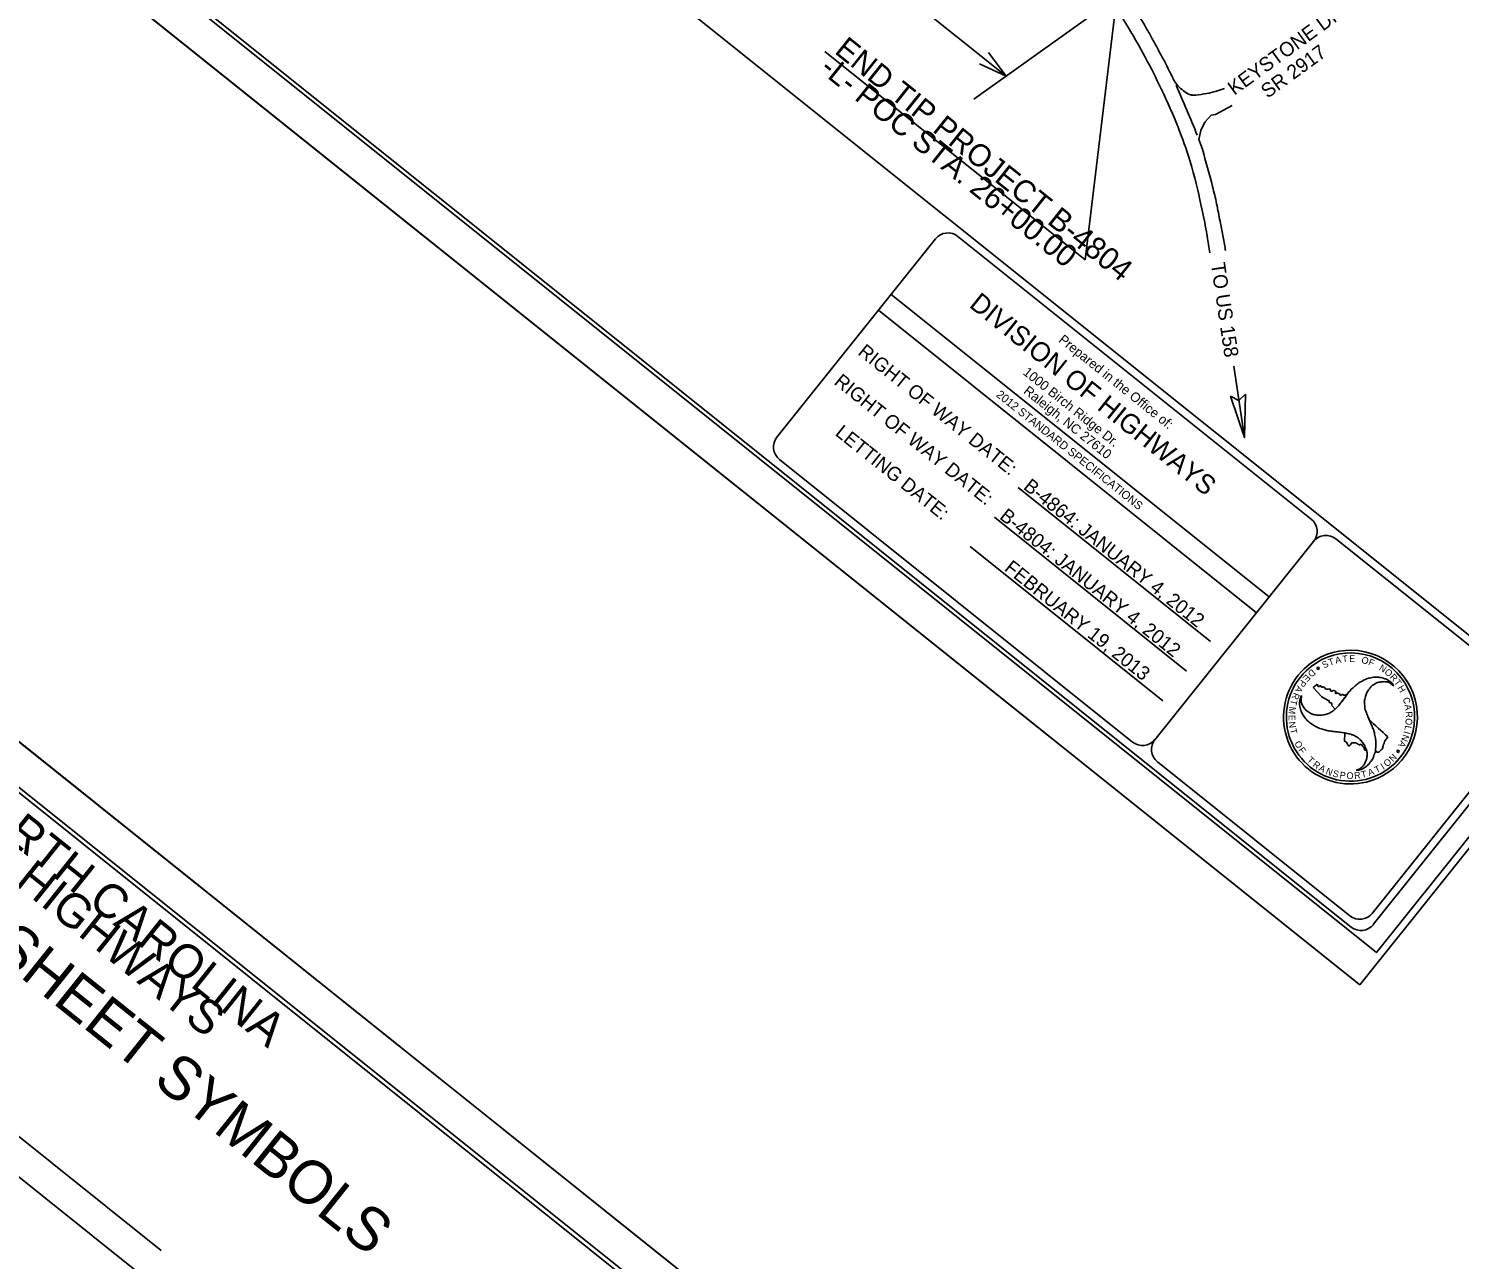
# Model space of a CAD drawing. Extents: x 1730256 to 1738218, y 910410 to 917906.
# Drawn here: x 1733718 to 1735520, y 913560 to 915111 of the extents above; entities that cross this region are included whole.
import ezdxf

# ---------------------------------------------------------------- set-up
doc = ezdxf.new("R2010")
doc.units = 0
for name, color, linetype in [('Old_Level_23', 7, 'Continuous'), ('Old_Level_3', 7, 'Continuous'), ('Old_Level_9', 7, 'Continuous'), ('Prop DSN Text', 7, 'Continuous'), ('Prop Terminator CELL', 7, 'Continuous'), ('Sheet Cutting Line CELL', 7, 'Continuous'), ('Sheet Data Field CELL', 7, 'Continuous'), ('Sheet Plot Border Inside CELL', 7, 'Continuous'), ('Sheet Plot Border Outside CELL', 7, 'Continuous'), ('Sheet Symbology CELL', 7, 'Continuous'), ('Sheet Title CELL', 7, 'Continuous')]:
    doc.layers.add(name, color=color, linetype=linetype)

msp = doc.modelspace()

# ---------------------------------------------------------------- linework, layer by layer
at = {"layer": 'Old_Level_23'}
for p, q in [((1734484.6, 915423.6), (1734949.5, 915051.5)), ((1735088.9, 915151.5), (1734908.9, 915022.4)), ((1735088.9, 915151.5), (1735048.8, 914820)), ((1734720.8, 915082.5), (1735048.8, 914820))]:
    msp.add_line(p, q, dxfattribs=at)
at = {"layer": 'Old_Level_3'}
msp.add_lwpolyline([(1735234.3, 915014.6), (1735213.2, 915003.1), (1735207.5, 915002.3), (1735199.9, 914993.4), (1735194.8, 914983), (1735192.3, 914971.6), (1735196.6, 914959.6)], dxfattribs=at)
msp.add_ellipse((1732344.7, 913726.7), major_axis=(-1157.9, 3394.9), ratio=0.865711, start_param=4.786277, end_param=4.805356, dxfattribs=at)
for points in [[(1735388.4, 915590.4), (1735416.8, 915551.2), (1735441.8, 915513.8), (1735465.3, 915471.6), (1735485, 915425.8), (1735499.5, 915381.4), (1735512.1, 915334.5), (1735524.2, 915290), (1735536.6, 915251.7), (1735553.3, 915211.2), (1735574, 915173.6), (1735599.6, 915136.9), (1735628.5, 915103.2), (1735661.8, 915070.2), (1735681.4, 915051.5)], [(1735374.5, 915580.4), (1735401.4, 915540.4), (1735425.3, 915502.3), (1735446.7, 915462.8), (1735465.8, 915420.2), (1735480.6, 915373.8), (1735493.3, 915328), (1735505.8, 915283.9), (1735518.6, 915242.7), (1735535.2, 915202.7), (1735557.3, 915162.9), (1735584.3, 915124.3), (1735613.8, 915089.7), (1735647.9, 915055.6), (1735667.7, 915037)], [(1734867.9, 915373.1), (1734891.7, 915356.8), (1734930.3, 915326), (1734970.3, 915292), (1735005.3, 915261.3), (1735024.1, 915243.4), (1735033.2, 915234.2), (1735042.1, 915224.8), (1735056.2, 915209.4), (1735069.7, 915193.5), (1735086.7, 915171.4), (1735102.7, 915148.8), (1735126, 915112.1), (1735140.9, 915084.9), (1735155.4, 915057.4), (1735158.1, 915051.7), (1735159.5, 915048.8), (1735160.9, 915045.9), (1735165.9, 915039.4), (1735172.8, 915033), (1735180.6, 915028.3), (1735182.6, 915027.8), (1735184.5, 915027.6), (1735188.4, 915027.7), (1735201.9, 915029.6), (1735214.3, 915032.5), (1735224.6, 915035.9)], [(1734858.2, 915360.7), (1734895.6, 915328.6), (1734934.2, 915297.2), (1734972.7, 915264.8), (1735005.9, 915234.2), (1735039.9, 915198.2), (1735072.4, 915158), (1735096.8, 915123.1), (1735122, 915080.1), (1735142.3, 915040.7), (1735163.9, 914992.3), (1735179.1, 914950.6), (1735193.6, 914895.6), (1735202.8, 914849.7), (1735206.1, 914828.7)], [(1735196.6, 914959.6), (1735209.5, 914912.3), (1735214.6, 914890.6), (1735216.8, 914879.6), (1735218.9, 914868.6), (1735220.7, 914859.7), (1735222.4, 914850.8), (1735225.5, 914833), (1735225.6, 914831.7)]]:
    msp.add_spline(points, degree=3, dxfattribs=at)
at = {"layer": 'Old_Level_9'}
msp.add_line((1735236.1, 914685.8), (1735249.8, 914595.9), dxfattribs=at)
at = {"layer": 'Prop DSN Text'}
msp.add_lwpolyline([(1734927.1, 915081.1), (1734949.5, 915051.5), (1734915.8, 915067)], dxfattribs=at)
at = {"layer": 'Prop Terminator CELL'}
msp.add_lwpolyline([(1735250.8, 914650.7), (1735249.8, 914595.9), (1735232.1, 914648.1), (1735242.6, 914642.7)], close=True, dxfattribs=at)
at = {"layer": 'Sheet Cutting Line CELL'}
for p, q in [((1732765.3, 916010.8), (1735394.8, 913906.4)), ((1734907.9, 913250.5), (1732278.3, 915354.9))]:
    msp.add_line(p, q, dxfattribs=at)
at = {"layer": 'Sheet Data Field CELL'}
msp.add_lwpolyline([(1736769.5, 915624), (1734139.9, 917728.5), (1732765.3, 916010.8), (1735394.8, 913906.4)], close=True, dxfattribs=at)
at = {"layer": 'Sheet Plot Border Inside CELL'}
for points in [[(1732813.6, 916029.6), (1735415.9, 913947), (1736734.4, 915594.6), (1734132.1, 917677.2)], [(1730952, 913656.1), (1733554.3, 911573.5), (1734872.8, 913221.1), (1732270.6, 915303.6)]]:
    msp.add_lwpolyline(points, close=True, dxfattribs=at)
at = {"layer": 'Sheet Plot Border Outside CELL'}
msp.add_lwpolyline([(1730903.7, 913637.3), (1733533.3, 911532.8), (1734907.9, 913250.5), (1732278.3, 915354.9)], close=True, dxfattribs=at)
at = {"layer": 'Sheet Symbology CELL'}
for p, q in [((1733885, 913571.6), (1733564.9, 913827.8)), ((1733860, 913540.4), (1733540, 913796.5))]:
    msp.add_line(p, q, dxfattribs=at)
msp.add_lwpolyline([(1734850.1, 913232.7), (1732507.9, 915107.2), (1731197, 913469.2), (1733539.2, 911594.7)], close=True, dxfattribs=at)
at = {"layer": 'Sheet Title CELL'}
for p, q in [((1733396.2, 916056.6), (1735613.6, 914282.1)), ((1734860.6, 914846.4), (1734660.7, 914596.5)), ((1734888.7, 914849.4), (1735333.7, 914493.3)), ((1735280.9, 914395.3), (1734804.6, 914776.4)), ((1735264.9, 914375.3), (1734788.7, 914756.5)), ((1734934.9, 914639.5), (1734934.9, 914639.5)), ((1734964.6, 914533.1), (1735206.8, 914339.2)), ((1734934.6, 914495.7), (1735176.8, 914301.8)), ((1735364.9, 914468.3), (1735607.3, 914274.3)), ((1734904, 914458.6), (1735146.8, 914264.3)), ((1735136.9, 914215.3), (1735336.8, 914465.2)), ((1735085.6, 914436.2), (1735085.6, 914436.2)), ((1735055.7, 914398.7), (1735055.7, 914398.7)), ((1735340.4, 914305.1), (1735341.7, 914305.8)), ((1735341.8, 914304.9), (1735340.4, 914305.1)), ((1735341.7, 914305.8), (1735341.5, 914307.2)), ((1735341.5, 914307.2), (1735342.6, 914306.2)), ((1735342, 914303.4), (1735341.8, 914304.9)), ((1735342.7, 914304.7), (1735342, 914303.4)), ((1735342.6, 914306.2), (1735343.8, 914306.8)), ((1735344.2, 914304.5), (1735342.7, 914304.7)), ((1735343.8, 914306.8), (1735343.2, 914305.5)), ((1735343.2, 914305.5), (1735344.2, 914304.5)), ((1735336.4, 914281.2), (1735340.2, 914284.6)), ((1735347, 914269.2), (1735336.4, 914281.2)), ((1735355.3, 914264.5), (1735347, 914269.2)), ((1735437.7, 914283.5), (1735437.4, 914283.5)), ((1735437.7, 914283.5), (1735437.4, 914283.5)), ((1735364, 914253.8), (1735359.4, 914258.7)), ((1735406.5, 914241.2), (1735406.5, 914241.2)), ((1735375.7, 914213.3), (1735376.3, 914223.7)), ((1735376.3, 914223.7), (1735376.3, 914223.7)), ((1735442.6, 914201.1), (1735441.3, 914200.5)), ((1735441.3, 914200.5), (1735442.7, 914200.3)), ((1735443.4, 914201.5), (1735442.4, 914202.6)), ((1735442.4, 914202.6), (1735442.6, 914201.1)), ((1735442.7, 914200.3), (1735442.9, 914198.8)), ((1735442.9, 914198.8), (1735443.6, 914200.1)), ((1735444.7, 914202.2), (1735443.4, 914201.5)), ((1735443.6, 914200.1), (1735445.1, 914199.9)), ((1735444, 914200.9), (1735444.7, 914202.2)), ((1735445.1, 914199.9), (1735444, 914200.9)), ((1735441.6, 914182.8), (1735441.6, 914182.8))]:
    msp.add_line(p, q, dxfattribs=at)
for points in [[(1733072.9, 915828.7), (1735383.9, 913979.1)], [(1735412, 913982.3), (1736699.2, 915590.6)], [(1734663.7, 914568.4), (1735108.7, 914212.2)], [(1735410.5, 913996.3), (1735610.4, 914246.2)], [(1735140, 914187.2), (1735382.4, 913993.2)]]:
    msp.add_lwpolyline(points, dxfattribs=at)
for centre, radius, start, end in [((1734876.2, 914833.9), 20, 51.3297, 141.3297), ((1734676.3, 914584), 20, 141.3297, 231.3297), ((1735321.2, 914477.7), 20, 321.3297, 51.3297), ((1735352.4, 914452.7), 20, 51.3297, 141.3297), ((1735383.2, 914243.8), 84.3, 313.7508, 133.7508), ((1735383.2, 914243.8), 80.8, 313.7508, 133.7508), ((1735383.2, 914243.8), 84.3, 133.7508, 313.7508), ((1735383.2, 914243.8), 80.8, 133.7508, 313.7508), ((1735721.7, 914554.9), 444.7, 219.4293, 219.5289), ((1735721.7, 914554.9), 444.7, 224.8684, 229.0744), ((1735121.3, 914227.9), 20, 231.3297, 321.3297), ((1735152.5, 914202.9), 20, 141.3297, 231.3297), ((1735394.9, 914008.9), 20, 231.3297, 321.3297), ((1735396.5, 913994.8), 20, 231.3297, 321.3297)]:
    msp.add_arc(centre, radius, start, end, dxfattribs=at)
for points in [[(1735437.4, 914283.5), (1735436.5, 914285.2), (1735432.5, 914289.1), (1735427.2, 914292), (1735426.7, 914292.1), (1735423.6, 914293.1), (1735419.9, 914293.8), (1735413.6, 914294.1), (1735407.3, 914292.9), (1735404.7, 914292.4), (1735402, 914291.2), (1735396.4, 914288.4), (1735391.6, 914285.1), (1735386.4, 914280.8), (1735382.2, 914276.6), (1735378.6, 914271.7), (1735374.9, 914266.8), (1735371.3, 914262.1), (1735367.4, 914257.3), (1735363.1, 914253.1), (1735362.7, 914252.7), (1735357.3, 914249.1), (1735351.5, 914247.1), (1735345.7, 914246.2), (1735342.8, 914246.1), (1735339.2, 914246.7), (1735337.2, 914246.9), (1735333.2, 914248.4), (1735328.2, 914251.6), (1735324.5, 914255.9), (1735322, 914260.4), (1735321, 914265.5), (1735321.5, 914270.8)], [(1735340.2, 914284.6), (1735340.4, 914285), (1735341.4, 914284.8), (1735342.3, 914282.4), (1735343.9, 914282.3), (1735344.6, 914283), (1735346, 914283), (1735346.9, 914281.6), (1735349.3, 914281.9), (1735350.4, 914281.1), (1735352.4, 914279.1), (1735357.2, 914279), (1735358.3, 914278.1), (1735357.9, 914277.2), (1735358.4, 914276.4), (1735361.4, 914277.3), (1735362, 914277.3), (1735364.6, 914276.2), (1735364.7, 914275.3), (1735363.9, 914274.3), (1735364, 914273.8), (1735365.1, 914273.6), (1735366.9, 914273.8), (1735369.3, 914273), (1735370.8, 914271), (1735372.5, 914272.1), (1735375.9, 914271.4), (1735377.2, 914271.8), (1735378.2, 914272.5)], [(1735390.5, 914176.7), (1735392.4, 914176.7), (1735397.8, 914178.3), (1735402.9, 914181.4), (1735403.4, 914181.7), (1735405.7, 914183.9), (1735408.2, 914186.8), (1735411.6, 914192.1), (1735413.7, 914198.1), (1735414.6, 914200.6), (1735414.9, 914203.7), (1735415.3, 914209.9), (1735414.9, 914215.7), (1735413.6, 914222.3), (1735412.1, 914228), (1735409.7, 914233.6), (1735407.3, 914239.3), (1735405.1, 914244.7), (1735402.8, 914250.5), (1735401.3, 914256.3), (1735401.3, 914256.9), (1735400.7, 914263.4), (1735402, 914269.5), (1735404, 914274.9), (1735405.5, 914277.4), (1735407.7, 914280.2), (1735408.9, 914281.9), (1735412.2, 914284.6), (1735417.5, 914287.3), (1735423, 914288.3), (1735428.2, 914288.3), (1735433.2, 914286.6), (1735437.4, 914283.5), (1735437.7, 914283.5)], [(1735321.5, 914270.8), (1735320.6, 914269.1), (1735319.2, 914263.6), (1735319.3, 914257.7), (1735319.4, 914257.2), (1735320.1, 914253.9), (1735321.4, 914250.4), (1735324.3, 914244.8), (1735328.4, 914240), (1735330.2, 914238), (1735332.7, 914236.2), (1735337.8, 914232.8), (1735343, 914230.2), (1735349.4, 914228), (1735355, 914226.5), (1735361.1, 914225.7), (1735367.3, 914225), (1735373.2, 914224.2), (1735379.2, 914223.2), (1735385, 914221.6), (1735385.6, 914221.4), (1735391.5, 914218.5), (1735396.1, 914214.5), (1735399.7, 914210.1), (1735401.3, 914207.5), (1735402.5, 914204.2), (1735403.4, 914202.2), (1735404.1, 914198), (1735403.8, 914192.1), (1735401.9, 914186.8), (1735399.3, 914182.4), (1735395.3, 914178.9), (1735390.5, 914176.7)], [(1735378.7, 914271.9), (1735378.6, 914271.7), (1735374.9, 914266.8), (1735371.3, 914262.1), (1735367.4, 914257.3), (1735364, 914253.8)], [(1735359.4, 914258.7), (1735359.9, 914260), (1735359.2, 914261.2), (1735357.4, 914261.8), (1735356.5, 914262.8), (1735356.3, 914264.6), (1735355.3, 914264.5)], [(1735414.8, 914201.7), (1735414.9, 914203.7), (1735415.3, 914209.9), (1735414.9, 914215.7), (1735413.6, 914222.3), (1735412.1, 914228), (1735409.7, 914233.6), (1735407.3, 914239.3), (1735406.5, 914241.2)], [(1735403.3, 914202.4), (1735401.7, 914201.9), (1735400.7, 914202.7), (1735400.5, 914205.6), (1735398.2, 914207.2), (1735397.8, 914208.6), (1735397.3, 914209.2), (1735394.1, 914208.9), (1735391.8, 914210.4), (1735386.5, 914211.4), (1735384.5, 914210.7), (1735381.8, 914207.7), (1735380.5, 914207.9), (1735379.7, 914209), (1735378.6, 914211.7), (1735375.7, 914213.3)], [(1735376.3, 914223.7), (1735379.2, 914223.2), (1735385, 914221.6), (1735385.6, 914221.4), (1735391.5, 914218.5), (1735396.1, 914214.5), (1735399.7, 914210.1), (1735401.3, 914207.5), (1735402.5, 914204.2), (1735403.3, 914202.4)], [(1735430.3, 914218.9), (1735427.1, 914214.1), (1735424.4, 914207.4), (1735423.1, 914203.5), (1735420.8, 914201.4), (1735417.6, 914199.4), (1735414.8, 914201.7)]]:
    msp.add_spline(points, degree=3, dxfattribs=at)

# ---------------------------------------------------------------- texts
at = {"layer": 'Old_Level_23'}
for s, p in [('END TIP PROJECT B-4804', (1734731.9, 915081.2)), ('-L- POC STA. 26+00.00', (1734713.2, 915057.8))]:
    msp.add_text(s, height=28, rotation=321.3297, dxfattribs=at).set_placement(p)
at = {"layer": 'Prop DSN Text'}
for s, rotation, p in [('KEYSTONE DRIVE', 35.9613, (1735236.9, 915026.6)), ('SR 2917', 35.9613, (1735278.7, 915022.8)), ('TO US 158', 278.3862, (1735207.2, 914815.2))]:
    msp.add_text(s, height=18, rotation=rotation, dxfattribs=at).set_placement(p)
at = {"layer": 'Sheet Data Field CELL'}
for s, p in [('B-4864: JANUARY 4, 2012 ', (1734970, 914532.1)), ('B-4804: JANUARY 4, 2012 ', (1734940, 914494.6)), ('FEBRUARY 19, 2013', (1734946.1, 914429.3))]:
    msp.add_text(s, height=17.5, rotation=321.3297, dxfattribs=at).set_placement(p)
at = {"layer": 'Sheet Symbology CELL'}
for s, height, p in [('CONVENTIONAL  PLAN SHEET SYMBOLS', 54.401, (1733024.1, 914462.4)), ('STATE OF NORTH CAROLINA', 42.838, (1733388.4, 914330.9)), ('DIVISION OF HIGHWAYS', 42.838, (1733415.8, 914259.9))]:
    msp.add_text(s, height=height, rotation=321.3297, dxfattribs=at).set_placement(p)
at = {"layer": 'Sheet Title CELL'}
for s, height, rotation, p in [('DIVISION OF HIGHWAYS', 24.374, 321.3297, (1734901.6, 914761.4)), ('Prepared in the Office of:', 11.999, 321.3297, (1735014.6, 914717.4)), ('RIGHT OF WAY DATE: ', 17.5, 321.3297, (1734761.5, 914701.6)), ('1000 Birch Ridge Dr.', 12, 321.3297, (1734969.6, 914676.5)), ('RIGHT OF WAY DATE: ', 17.5, 321.3297, (1734731.5, 914664.1)), ('2012 STANDARD SPECIFICATIONS', 10.4, 321.3297, (1734936, 914648.5)), ('Raleigh, NC 27610', 12, 321.3297, (1734970.4, 914652.8)), ('LETTING DATE:', 17.5, 321.3297, (1734732.9, 914599.8)), ('T', 8.39, 5.0234, (1735373.3, 914312.7)), ('E', 8.38, 357.9077, (1735381.5, 914313.4)), ('D', 8.41, 221.6038, (1735334.6, 914304.9)), ('S', 8.4, 25.5071, (1735349.8, 914304.9)), ('T', 8.43, 19.1309, (1735357, 914308.3)), ('A', 8.44, 12.0786, (1735364.8, 914310.9)), ('O', 8.42, 345.9684, (1735396.4, 914312.1)), ('F', 8.43, 338.8215, (1735405, 914309.9)), ('N', 8.41, 326.7346, (1735418.4, 914303.9)), ('O', 8.43, 319.2365, (1735425.2, 914299.4)), ('P', 8.41, 235.4241, (1735321.4, 914291.5)), ('E', 8.37, 227.8917, (1735327.4, 914298.4)), ('R', 8.41, 312.6265, (1735432, 914293.6)), ('T', 8.43, 305.9769, (1735437.4, 914287.6)), ('R', 8.41, 249.0853, (1735311.8, 914275.3)), ('A', 8.4, 242.0167, (1735316.3, 914284.1)), ('H', 8.4, 298.8922, (1735442.2, 914280.9)), ('C', 8.39, 286.5498, (1735448.9, 914267.3)), ('M', 8.39, 262.9709, (1735306.3, 914257.3)), ('T', 8.4, 255.7358, (1735308.5, 914266.6)), ('A', 8.4, 279.0528, (1735451.2, 914259.2)), ('R', 8.4, 272.6889, (1735452.6, 914250.7)), ('E', 8.39, 270.4376, (1735305.2, 914246.6)), ('N', 8.43, 277.4092, (1735305.3, 914237.6)), ('L', 8.39, 259.3356, (1735452.3, 914233.7)), ('O', 8.43, 265.5693, (1735452.9, 914242.6)), ('T', 8.4, 284.2512, (1735306.7, 914228.2)), ('O', 8.41, 297.5549, (1735312.2, 914211.1)), ('A', 8.41, 242.2142, (1735446.7, 914214.9)), ('N', 8.41, 249.6461, (1735449.7, 914222.6)), ('I', 8.42, 255.3462, (1735450.8, 914226.6)), ('F', 8.4, 304.7201, (1735317.1, 914202.2)), ('N', 8.41, 45.9589, (1735436.8, 914186.8)), ('T', 8.38, 317.6293, (1735327.7, 914188.7)), ('R', 8.42, 324.586, (1735334.9, 914182.3)), ('A', 8.38, 331.3391, (1735342.5, 914177.1)), ('N', 8.38, 338.3707, (1735351.3, 914172.4)), ('A', 8.43, 20.841, (1735406.8, 914169.2)), ('T', 8.4, 27.9254, (1735416.1, 914172.8)), ('I', 8.43, 33.5753, (1735424.5, 914177.3)), ('O', 8.38, 38.7109, (1735429, 914180.4)), ('S', 8.37, 345.5812, (1735360.2, 914169.1)), ('P', 8.41, 352.773, (1735369.2, 914166.8)), ('O', 8.43, 359.465, (1735378.2, 914165.8)), ('R', 8.42, 6.6541, (1735388.3, 914165.7)), ('T', 8.38, 12.7539, (1735397.6, 914166.9))]:
    msp.add_text(s, height=height, rotation=rotation, dxfattribs=at).set_placement(p)

doc.saveas('drawing.dxf')
